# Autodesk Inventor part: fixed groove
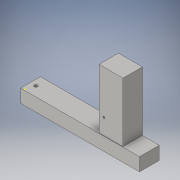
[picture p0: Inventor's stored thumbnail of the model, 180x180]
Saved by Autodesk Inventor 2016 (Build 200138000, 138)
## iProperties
Created: 2020-02
Part Number: fixed groove
Material: Generic
Document SubType Name: Modeling
Designer: merlin
Density: 1 g/cm^3
Appearance: Default
Author: merlin
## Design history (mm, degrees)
sketch "Sketch1"
  geometry: L1 (14.287, 1.587)-(-442.912, 1.587); L2 (-442.912, 1.587)-(-442.912, -74.612); L3 (-442.912, -74.612)-(14.287, -74.612); L4 (14.287, -74.612)-(14.287, 1.587); 1 further point
  constraints: 8 end point, 2 parallel, 1 horizontal, 1 perpendicular
  dimensions: "d0" = 457.2 distance of L3.end L2.end; "d1" = 76.2 distance of L2.end L1.end
extrude "Extrusion1" new body sketch "Sketch1" distance "d2" = 50.8; taper "d3" = 0 deg
sketch "Sketch2"
  geometry: C1 r 6.35 at (7.938, 34.925); 1 further point
  constraints: 1 centre point
  dimensions: "d4" = 12.7 diameter of C1
extrude "Extrusion2" join sketch "Sketch2" distance "d5" = 2.54; taper "d6" = 0 deg
sketch "Sketch3"
  geometry: 1 further point
sketch "Sketch4"
  geometry: 1 further point
sketch "Sketch5"
  geometry: C1 r 6.35 at (0, 0); 1 further point
  constraints: 1 centre point
hole "Hole1" sketch "Sketch5" at (0, 0) diameter "d7" = 12.7; stored, may be unused: countersink angle "d11" = 82 deg, drill point angle "d13" = 118 deg; dims "d8" = 19.05, "d9" = 9.525, "d10" = 6.35, "d12" = 12.7
sketch "Sketch6"
  geometry: L1 (442.912, 74.612)-(-14.287, 74.612) reference; L2 (285.75, 74.612)-(377.825, 74.612); L3 (377.825, 74.612)-(377.825, 0); L4 (377.825, 0)-(285.75, 0); L5 (285.75, 0)-(285.75, 74.612); 1 further point
  constraints: 8 end point, 2 parallel, 1 horizontal, 1 perpendicular, 1 point on line
extrude "Extrusion3" join sketch "Sketch6" distance "d14" = 228.6; taper "d15" = 0 deg
sketch "Sketch7"
  geometry: 1 further point
sketch "Sketch8"
  geometry: L1 (66.675, 44.45)-(9.525, 44.45); L2 (9.525, 44.45)-(9.525, 77.788); L3 (9.525, 77.788)-(66.675, 77.788); L4 (66.675, 77.788)-(66.675, 44.45); 1 further point
  constraints: 8 end point, 2 parallel, 1 horizontal, 1 perpendicular
extrude "Extrusion4" cut sketch "Sketch8" distance "d16" = 38.1; taper "d17" = 0 deg
sketch "Sketch9"
  geometry: 1 further point
sketch "Sketch10"
  geometry: C1 r 3.969 at (19.05, 61.119); 1 further point
  constraints: 1 centre point
hole "Hole2" sketch "Sketch10" at (19.05, 61.119) diameter "d18" = 7.62; stored, may be unused: countersink angle "d22" = 82 deg, drill point angle "d24" = 118 deg; dims "d19" = 19.05, "d20" = 9.525, "d21" = 6.35, "d23" = 25.4
body "Solid1"
